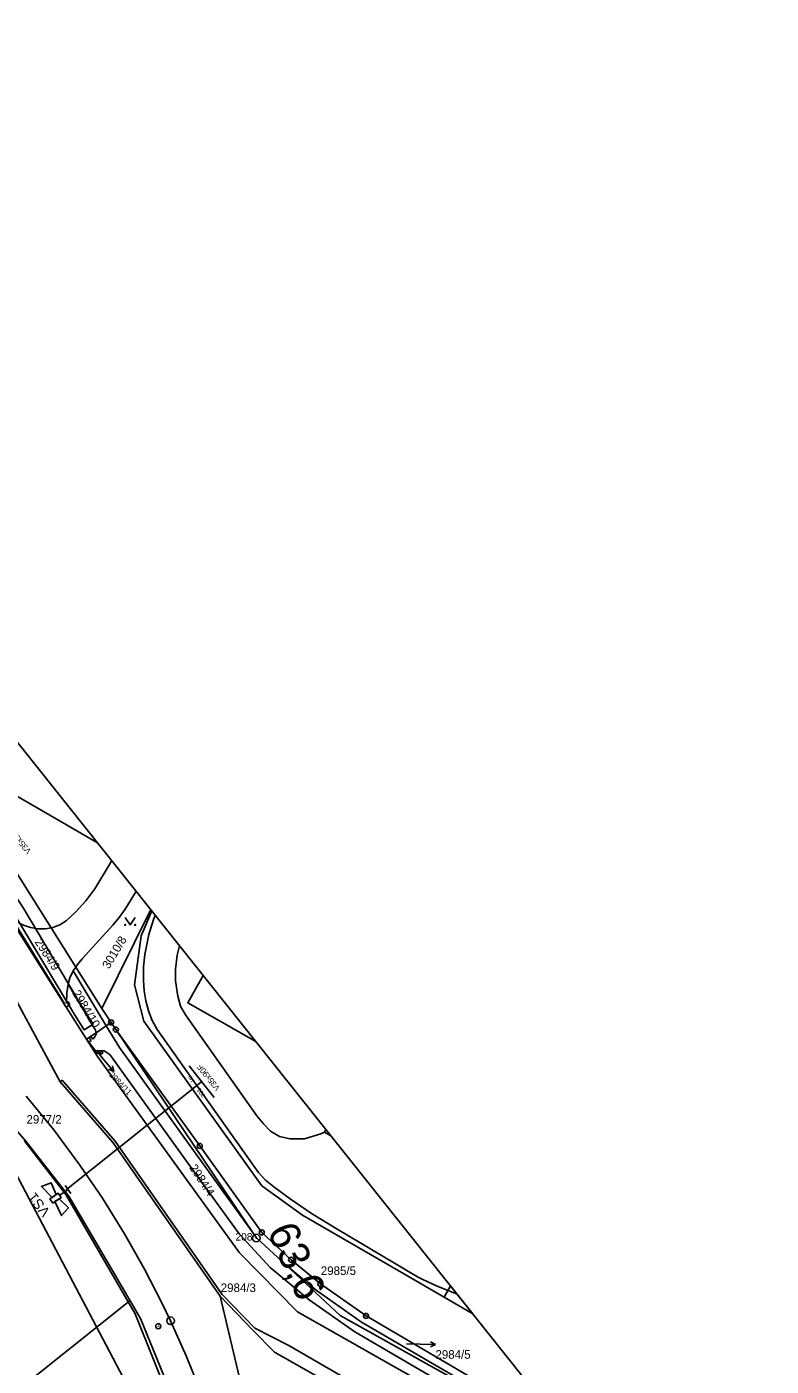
# Model space of a CAD drawing. Extents: x -620412 to -620034, y -1122986 to -1122565.
# Drawn here: x -620181.4 to -620034.3, y -1122830 to -1122565.2 of the extents above; entities that cross this region are included whole.
import ezdxf

# ---------------------------------------------------------------- set-up
doc = ezdxf.new("R2010")
doc.units = 0
for name, color, linetype in [('HranDP', 7, 'Continuous'), ('Hranice parcel', 7, 'Continuous'), ('Parcelní čísla', 7, 'Continuous'), ('Pop  PČ popisy', 7, 'Continuous'), ('Rámečky-tisk', 7, 'Continuous'), ('Vnitřní kresba', 7, 'Continuous'), ('Vrstva 1', 7, 'Continuous'), ('Vrstva 2', 7, 'Continuous'), ('Vrstva 3', 7, 'Continuous'), ('Vrstva 33', 7, 'Continuous'), ('Vrstva 7', 7, 'Continuous'), ('Věcná břemena k části', 7, 'Continuous'), ('Značky bodu BP', 7, 'Continuous'), ('Značky kultur', 7, 'Continuous')]:
    doc.layers.add(name, color=color, linetype=linetype)

msp = doc.modelspace()

# ---------------------------------------------------------------- linework, layer by layer
at = {"layer": 'HranDP'}
for points in [[(-620197.33, -1122735.44), (-620187.9, -1122749.66), (-620174.83, -1122773.82), (-620164.34, -1122785.91), (-620143.18, -1122816.17)], [(-620152.84, -1122837.4), (-620159.98, -1122819.68), (-620173.68, -1122796.12), (-620181.92, -1122785.4)], [(-620143.18, -1122816.17), (-620134.66, -1122852.11), (-620129.18, -1122882.66), (-620128.4, -1122892.9)]]:
    msp.add_lwpolyline(points, dxfattribs=at)
at = {"layer": 'Hranice parcel'}
for p, q in [((-620176.62, -1122743.36), (-620186.47, -1122727.64)), ((-620156.92, -1122739.77), (-620166.6, -1122759.34)), ((-620176.62, -1122743.36), (-620171.74, -1122751.13)), ((-620171.74, -1122751.13), (-620166.6, -1122759.34)), ((-620164.75, -1122762.08), (-620166.6, -1122759.34)), ((-620163.81, -1122763.48), (-620164.75, -1122762.08))]:
    msp.add_line(p, q, dxfattribs=at)
for points in [[(-620195.75, -1122691.03), (-620197.92, -1122694.75), (-620198.58, -1122696.08), (-620199.01, -1122697.5), (-620199.13, -1122698.99), (-620198.88, -1122700.47), (-620198.25, -1122701.83), (-620197.37, -1122703.03), (-620195.84, -1122704.31), (-620190.67, -1122707.32), (-620190.09, -1122707.94), (-620189.82, -1122708.78), (-620189.94, -1122709.65), (-620191.6, -1122712.59), (-620176.88, -1122721.09), (-620167.45, -1122726.54)], [(-620164.67, -1122730.04), (-620164.86, -1122730.54), (-620167.98, -1122735.66), (-620169.77, -1122738.05), (-620171.8, -1122740.25), (-620173.6, -1122742), (-620174.86, -1122742.79), (-620176.26, -1122743.3), (-620176.62, -1122743.36)], [(-620197.33, -1122735.44), (-620187.9, -1122749.66), (-620174.83, -1122773.82), (-620164.34, -1122785.91), (-620143.18, -1122816.17)], [(-620159.82, -1122736.13), (-620160.91, -1122737.97), (-620161.97, -1122739.66), (-620163.14, -1122741.3), (-620164.41, -1122742.85), (-620170.46, -1122749.51), (-620171.42, -1122750.65), (-620171.74, -1122751.13)], [(-620173.24, -1122754.52), (-620173.48, -1122756.2), (-620173.53, -1122758.23), (-620173.22, -1122758.03), (-620172.91, -1122758.59), (-620173.61, -1122759.06), (-620173.64, -1122759.08), (-620174, -1122758.53), (-620173.96, -1122758.5), (-620173.87, -1122758.44), (-620183.92, -1122742.28), (-620184.05, -1122742.35), (-620184.39, -1122741.79), (-620183.63, -1122741.31), (-620183.27, -1122741.89), (-620183.57, -1122742.07), (-620182.08, -1122742.82), (-620180.68, -1122743.31), (-620179.21, -1122743.55), (-620177.73, -1122743.55), (-620176.62, -1122743.36)], [(-620093.25, -1122819.69), (-620107.97, -1122811.15), (-620126.88, -1122800.18), (-620134.93, -1122794.41), (-620148.77, -1122775.1), (-620158.3, -1122761.8), (-620160.13, -1122754.62), (-620158.82, -1122744.94), (-620156.7, -1122740.04)], [(-620173.24, -1122754.52), (-620172.87, -1122753.23), (-620172.25, -1122751.89), (-620171.74, -1122751.13)], [(-620167.73, -1122764.1), (-620167.81, -1122763.6), (-620173.24, -1122754.52)], [(-620146.52, -1122752.83), (-620149.58, -1122758.23), (-620136.16, -1122765.83)], [(-620164.75, -1122762.08), (-620165.7, -1122762.73), (-620167.73, -1122764.1)], [(-620169.18, -1122765.95), (-620169.61, -1122765.37), (-620167.73, -1122764.1)], [(-620072.47, -1122846.25), (-620119.48, -1122820.03), (-620130.17, -1122810.08), (-620136, -1122804.68), (-620136.79, -1122803.52), (-620163.81, -1122763.48)], [(-620074.69, -1122842.98), (-620093.24, -1122832.45), (-620114.36, -1122820.1), (-620123.37, -1122813.77), (-620129.15, -1122808.98), (-620134.98, -1122803.58), (-620147.22, -1122786.5), (-620163.81, -1122763.48)], [(-620169.18, -1122765.95), (-620167.86, -1122767.72), (-620166.7, -1122767.69)], [(-620166.7, -1122767.69), (-620166.41, -1122768.09), (-620166.72, -1122768.33), (-620167.06, -1122767.87), (-620167.55, -1122768.23), (-620169.18, -1122765.95)], [(-620074.02, -1122848.16), (-620095.17, -1122835.78), (-620116.57, -1122823.25), (-620125.58, -1122816.92), (-620133.3, -1122810.53), (-620139.43, -1122803.84), (-620150.35, -1122788.75), (-620165.02, -1122768.39), (-620166.09, -1122767.67), (-620166.7, -1122767.69)], [(-620122.29, -1122783.24), (-620122.58, -1122783.75), (-620121.31, -1122784.47)], [(-620152.84, -1122837.4), (-620159.98, -1122819.68), (-620173.68, -1122796.12), (-620181.92, -1122785.4)], [(-620143.18, -1122816.17), (-620134.66, -1122852.11), (-620129.18, -1122882.66), (-620128.4, -1122892.9)], [(-620080.86, -1122856.55), (-620132.47, -1122827.27), (-620136.72, -1122822.9), (-620143.18, -1122816.17)]]:
    msp.add_lwpolyline(points, dxfattribs=at)
at = {"layer": 'Pop  PČ popisy'}
for p, q in [((-620167.46, -1122767.92), (-620166.15, -1122769.46)), ((-620166.15, -1122769.46), (-620164.22, -1122771.76)), ((-620164.22, -1122771.76), (-620164.48, -1122770.67)), ((-620164.22, -1122771.76), (-620165.25, -1122771.31)), ((-620106.35, -1122825.61), (-620103.63, -1122825.67)), ((-620103.63, -1122825.67), (-620100.63, -1122825.72)), ((-620100.63, -1122825.72), (-620101.64, -1122826.21)), ((-620100.63, -1122825.72), (-620101.62, -1122825.2))]:
    msp.add_line(p, q, dxfattribs=at)
at = {"layer": 'Rámečky-tisk'}
msp.add_lwpolyline([(-620412.11, -1122657.76), (-620150.41, -1122986.26), (-620034.26, -1122893.74), (-620295.96, -1122565.23)], dxfattribs=at)
at = {"layer": 'Vnitřní kresba'}
for p, q in [((-620191.31, -1122731.11), (-620173.96, -1122758.5)), ((-620157.32, -1122744.66), (-620156.36, -1122741.72)), ((-620156.36, -1122741.72), (-620156.01, -1122740.92)), ((-620158.07, -1122748.62), (-620157.32, -1122744.66)), ((-620151.67, -1122748.77), (-620151.22, -1122746.92)), ((-620158.33, -1122751.09), (-620158.07, -1122748.62)), ((-620152.03, -1122751.56), (-620151.67, -1122748.77)), ((-620172.25, -1122751.89), (-620165.7, -1122762.73)), ((-620158.37, -1122753.78), (-620158.33, -1122751.09)), ((-620152.03, -1122753.86), (-620152.03, -1122751.56)), ((-620158.2, -1122755.8), (-620158.37, -1122753.78)), ((-620151.58, -1122756.91), (-620152.03, -1122753.86)), ((-620157.86, -1122757.82), (-620158.2, -1122755.8)), ((-620157.34, -1122759.76), (-620157.86, -1122757.82)), ((-620151.04, -1122758.86), (-620151.58, -1122756.91)), ((-620173.61, -1122759.06), (-620169.61, -1122765.37)), ((-620156.64, -1122761.69), (-620157.34, -1122759.76)), ((-620150.03, -1122760.6), (-620151.04, -1122758.86)), ((-620135.93, -1122780.56), (-620150.03, -1122760.6)), ((-620165.7, -1122762.73), (-620163.11, -1122767.02)), ((-620155.67, -1122763.48), (-620156.64, -1122761.69)), ((-620169.61, -1122765.37), (-620167.41, -1122768.84)), ((-620168.7, -1122765.62), (-620169.18, -1122765.95)), ((-620168.75, -1122764.87), (-620169.05, -1122765.1)), ((-620169.05, -1122765.1), (-620168.7, -1122765.62)), ((-620168.38, -1122765.37), (-620168.75, -1122764.87)), ((-620167.95, -1122764.93), (-620168.38, -1122765.37)), ((-620167.68, -1122764.39), (-620167.95, -1122764.93)), ((-620167.73, -1122764.1), (-620167.68, -1122764.39)), ((-620136.78, -1122790.07), (-620155.67, -1122763.48)), ((-620163.11, -1122767.02), (-620148.44, -1122787.38)), ((-620167.41, -1122768.84), (-620139.39, -1122807.63)), ((-620174.83, -1122773.82), (-620174.45, -1122773.49)), ((-620174.45, -1122773.49), (-620163.96, -1122785.58)), ((-620134.64, -1122782.1), (-620135.93, -1122780.56)), ((-620133.21, -1122783.55), (-620134.64, -1122782.1)), ((-620131.49, -1122784.61), (-620133.21, -1122783.55)), ((-620163.96, -1122785.58), (-620142.77, -1122815.89)), ((-620185.65, -1122788.07), (-620157.72, -1122840.99)), ((-620148.44, -1122787.38), (-620136.79, -1122803.52)), ((-620135.58, -1122791.72), (-620136.78, -1122790.07)), ((-620134.2, -1122793.25), (-620135.58, -1122791.72)), ((-620132.61, -1122794.57), (-620134.2, -1122793.25)), ((-620129.33, -1122796.98), (-620132.61, -1122794.57)), ((-620125.13, -1122799.85), (-620129.33, -1122796.98)), ((-620119.93, -1122803.03), (-620125.13, -1122799.85)), ((-620104.17, -1122812.35), (-620119.93, -1122803.03)), ((-620139.39, -1122807.63), (-620127.92, -1122819.29)), ((-620124.23, -1122815), (-620130.17, -1122810.08)), ((-620103.27, -1122812.85), (-620104.17, -1122812.35)), ((-620102.16, -1122813.38), (-620103.27, -1122812.85)), ((-620100.32, -1122814.22), (-620102.16, -1122813.38)), ((-620142.77, -1122815.89), (-620136.36, -1122822.55)), ((-620115.22, -1122821.33), (-620124.23, -1122815)), ((-620098.43, -1122814.97), (-620100.32, -1122814.22)), ((-620096.37, -1122815.78), (-620098.43, -1122814.97)), ((-620127.92, -1122819.29), (-620075.39, -1122849.03)), ((-620093.98, -1122833.75), (-620115.22, -1122821.33)), ((-620136.36, -1122822.55), (-620129.64, -1122825.94)), ((-620129.64, -1122825.94), (-620104.21, -1122840.64))]:
    msp.add_line(p, q, dxfattribs=at)
msp.add_lwpolyline([(-620122.58, -1122783.75), (-620123.27, -1122784.1), (-620126.53, -1122785.08), (-620129.37, -1122785.1), (-620131.49, -1122784.61)], dxfattribs=at)
at = {"layer": 'Vrstva 1'}
msp.add_line((-620173.25, -1122795.11), (-620173.84, -1122795.49), dxfattribs=at)
for points in [[(-620173.84, -1122795.49), (-620176.67, -1122791.87), (-620181.59, -1122785.57), (-620185.43, -1122781.13), (-620190.33, -1122775.52), (-620190.05, -1122772.28), (-620198.93, -1122763.63), (-620211.63, -1122752.65), (-620228.5, -1122738.51), (-620248.32, -1122722.77)], [(-620181.54, -1122776.64), (-620176.09, -1122783.33), (-620170.93, -1122790.27), (-620166.46, -1122796.85), (-620162.11, -1122803.84), (-620158.13, -1122810.88), (-620154.63, -1122817.64), (-620152.99, -1122821.05), (-620149.89, -1122827.96), (-620146.96, -1122835.3)], [(-620151.28, -1122839.45), (-620151.64, -1122838.53), (-620158.91, -1122820.61), (-620164.59, -1122810.94), (-620173.13, -1122796.4), (-620173.84, -1122795.49)]]:
    msp.add_lwpolyline(points, dxfattribs=at)
at = {"layer": 'Vrstva 2'}
for p, q in [((-620173.82, -1122794.29), (-620172.68, -1122795.93)), ((-620172.68, -1122795.93), (-620173.82, -1122794.29)), ((-620174.9, -1122796.25), (-620173.25, -1122795.11)), ((-620174.9, -1122796.25), (-620173.25, -1122795.11))]:
    msp.add_line(p, q, dxfattribs=at)
for points in [[(-620176.42, -1122796.69), (-620178.53, -1122794.5), (-620176.6, -1122793.78), (-620175.59, -1122796.12)], [(-620176.83, -1122796.97), (-620176.26, -1122797.8), (-620174.61, -1122796.66), (-620175.18, -1122795.84)], [(-620176.26, -1122797.8), (-620176.83, -1122796.97), (-620175.18, -1122795.84), (-620174.61, -1122796.66)], [(-620175.85, -1122797.51), (-620174.55, -1122800.26), (-620173.19, -1122798.72), (-620175.03, -1122796.94)]]:
    msp.add_lwpolyline(points, close=True, dxfattribs=at)
at = {"layer": 'Vrstva 33'}
for p, q in [((-620149.34, -1122770.68), (-620144.36, -1122776.94)), ((-620173.55, -1122795.08), (-620146.85, -1122773.81)), ((-620173.55, -1122795.08), (-620173.58, -1122795.32)), ((-620161, -1122817.05), (-620224.35, -1122867.51))]:
    msp.add_line(p, q, dxfattribs=at)
at = {"layer": 'Vrstva 7'}
msp.add_line((-620155.44, -1122822.09), (-620155.4, -1122822.18), dxfattribs=at)
for centre, radius in [((-620152.99, -1122821.05), 0.75), ((-620155.42, -1122822.14), 0.5)]:
    msp.add_circle(centre, radius, dxfattribs=at)
at = {"layer": 'Věcná břemena k části'}
msp.add_line((-620093.25, -1122819.69), (-620097.64, -1122814.18), dxfattribs=at)
msp.add_line((-620093.25, -1122819.69), (-620097.64, -1122814.18), dxfattribs=at)
msp.add_line((-620093.25, -1122819.69), (-620097.64, -1122814.18), dxfattribs=at)
msp.add_line((-620093.25, -1122819.69), (-620097.64, -1122814.18), dxfattribs=at)
msp.add_lwpolyline([(-620187.14, -1122731.99), (-620188.79, -1122733.18), (-620187.68, -1122734.99), (-620184.01, -1122740.44), (-620172.01, -1122760.53), (-620170.08, -1122763.54), (-620168.3, -1122762.4), (-620170.19, -1122759.45), (-620182.21, -1122739.32)], close=True, dxfattribs=at)
msp.add_lwpolyline([(-620097.64, -1122814.18), (-620098.89, -1122816.42), (-620093.25, -1122819.69)], dxfattribs=at)
msp.add_lwpolyline([(-620097.64, -1122814.18), (-620098.89, -1122816.42), (-620093.25, -1122819.69)], dxfattribs=at)
msp.add_lwpolyline([(-620097.64, -1122814.18), (-620098.89, -1122816.42), (-620093.25, -1122819.69)], dxfattribs=at)
msp.add_lwpolyline([(-620097.64, -1122814.18), (-620098.89, -1122816.42), (-620093.25, -1122819.69)], dxfattribs=at)
at = {"layer": 'Značky bodu BP'}
for centre, radius in [((-620164.75, -1122762.08), 0.5), ((-620164.75, -1122762.08), 0.0303), ((-620163.81, -1122763.48), 0.5), ((-620163.81, -1122763.48), 0.0303), ((-620147.22, -1122786.5), 0.5), ((-620147.22, -1122786.5), 0.0303), ((-620136.05, -1122804.7), 0.75), ((-620136.05, -1122804.7), 0.03), ((-620134.98, -1122803.58), 0.5), ((-620134.98, -1122803.58), 0.0303), ((-620129.15, -1122808.98), 0.5), ((-620129.15, -1122808.98), 0.0303), ((-620123.37, -1122813.77), 0.5), ((-620123.37, -1122813.77), 0.0303), ((-620114.36, -1122820.1), 0.5), ((-620114.36, -1122820.1), 0.0303)]:
    msp.add_circle(centre, radius, dxfattribs=at)
at = {"layer": 'Značky kultur'}
msp.add_lwpolyline([(-620161.99, -1122741.3), (-620160.99, -1122742.8), (-620159.99, -1122741.3)], dxfattribs=at)
for centre in [(-620161.99, -1122742.8), (-620159.99, -1122742.8)]:
    msp.add_circle(centre, 0.1, dxfattribs=at)

# ---------------------------------------------------------------- texts
at = {"layer": 'Parcelní čísla'}
for s, height, rotation, p in [('2984/9', 1.7, 303, (-620179.93, -1122746.16)), ('3010/8', 1.7, 59, (-620165.17, -1122751.62)), ('2984/10', 1.7, 301, (-620172.47, -1122756.29)), ('2984/11', 1.139, 314, (-620165.2, -1122772.57)), ('2984/4', 1.7, 303, (-620149.36, -1122790.78))]:
    msp.add_text(s, height=height, rotation=rotation, dxfattribs=at).set_placement(p)
for s, p in [('2977/2', (-620181.47, -1122782.09)), ('2985/5', (-620123.29, -1122812.01)), ('2984/3', (-620143.07, -1122815.38)), ('2984/5', (-620100.63, -1122828.57))]:
    msp.add_text(s, height=1.7, dxfattribs=at).set_placement(p)
at = {"layer": 'Vrstva 3'}
msp.add_text('VS1', height=2, rotation=128.542, dxfattribs=at).set_placement((-620176.65, -1122799.48))
at = {"layer": 'Vrstva 33'}
for s, height, p in [('V35x50 1Z1', 1.15, (-620180.46, -1122728.17)), ('V35x90F', 1.15, (-620143.14, -1122775.01)), ('1m', 0.75, (-620148.25, -1122773.65)), ('701', 0.9, (-620145.96, -1122776.52))]:
    msp.add_text(s, height=height, rotation=128.542, dxfattribs=at).set_placement(p)
at = {"layer": 'Vrstva 7'}
msp.add_text('63,6', height=6, rotation=294.1767, dxfattribs=at).set_placement((-620133.97, -1122803.32))
at = {"layer": 'Značky bodu BP'}
msp.add_text('208', height=1.5, dxfattribs=at).set_placement((-620140.15, -1122805.2))

doc.saveas('drawing.dxf')
